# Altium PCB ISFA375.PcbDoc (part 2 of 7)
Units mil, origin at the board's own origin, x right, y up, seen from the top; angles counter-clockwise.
Board outline 5615 x 5520 mil, 6 copper layers (Top_SL, GND, POWER, Signal_Layer, GND2, Bottom_SL), stack 60.472 mil thick; 494 components, 307 nets, 1648 pads, 755 vias.
Unrouted connection lines stored in the file: 315.
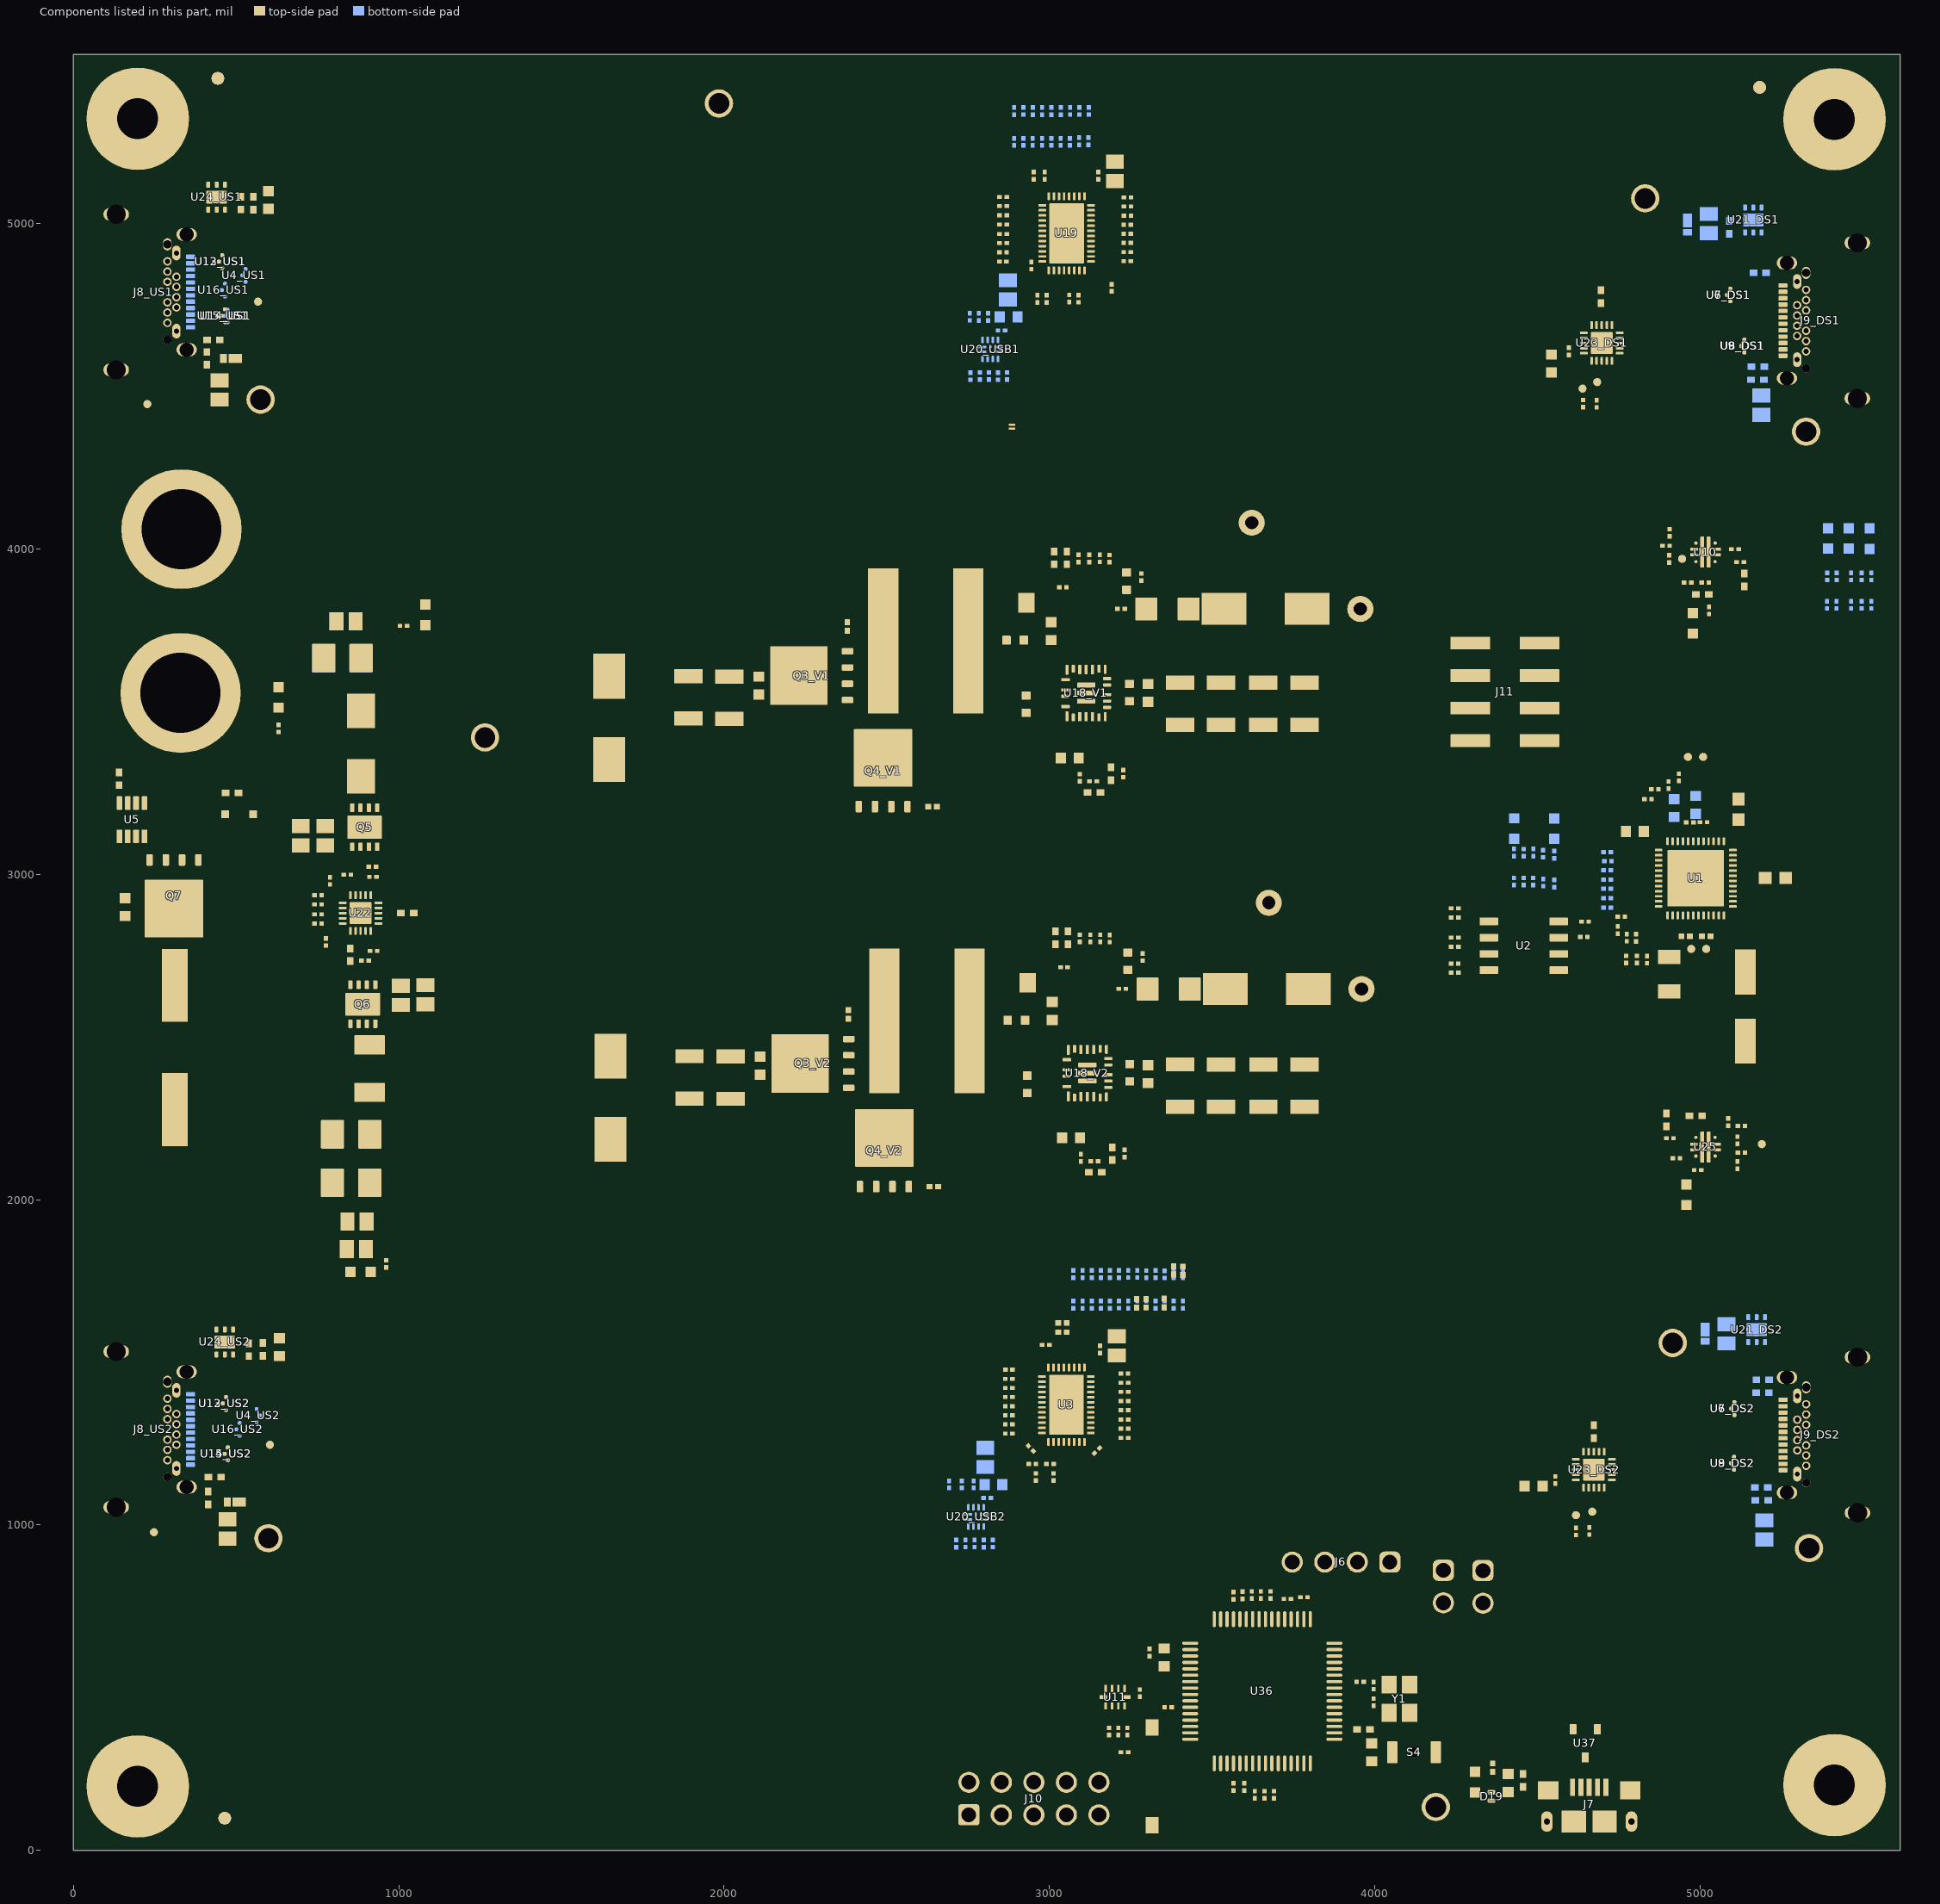
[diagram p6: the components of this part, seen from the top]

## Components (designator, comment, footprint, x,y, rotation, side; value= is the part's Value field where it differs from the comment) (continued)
R173 "RC0201FR-07470RL" 0201L 5464.61,3916.09 r270 bottom value=470
S1 "CHS-01TB" SW_CHS-01TB 3316.08,227.38 r180 top
S4 "B3U-1000P-B" FP-B3U-1000P-B_SMT_SW_3MM_2MM5-MFG 4121.01,301.56 r180 top
TP1 "TESTPOINT" TP_25MIL-SMT 4963,3361.17 r180 top
TP2 "TESTPOINT" TP_25MIL-SMT 5009.5,3361.17 r180 top
TP4 "TESTPOINT" TP_25MIL-SMT 4973,2771 r180 top
TP5 "TESTPOINT" TP_25MIL-SMT 5019,2771 r180 top
TP6 "5005" Keystone5005 1984,5369.96 r90 top
TP7_V1 "5003" Keystone5003 3622,4080.88 r90 top (schematic designator TP7)
TP7_V2 "5003" Keystone5003 3674.46,2912.88 r90 top (schematic designator TP7)
TP8_V1 "5003" Keystone5003 3955.74,3815.9 r90 top (schematic designator TP8)
TP8_V2 "5003" Keystone5003 3959.53,2647.9 r90 top (schematic designator TP8)
TP9_US1 "5005" Keystone5005 575.03,4459.47 r90 top (schematic designator TP9)
TP9_US2 "5005" Keystone5005 599.03,959.47 r90 top (schematic designator TP9)
TP10_DS1 "5005" Keystone5005 4831.4,5078 r90 top (schematic designator TP10)
TP10_DS2 "5005" Keystone5005 4916.03,1559.79 r90 top (schematic designator TP10)
TP11_DS1 "5006" Keystone5006 5326.17,4360.98 r90 top (schematic designator TP11)
TP11_DS2 "5006" Keystone5006 5335.13,928.9 r90 top (schematic designator TP11)
TP12 "5005" Keystone5005 4187.94,133.36 r0 top
TP13_DS1 "TESTPOINT" TP_25MIL-SMT 4683.89,4513.37 r180 top (schematic designator TP13)
TP13_DS2 "TESTPOINT" TP_25MIL-SMT 4668.76,1041.1 r180 top (schematic designator TP13)
TP14_DS1 "TESTPOINT" TP_25MIL-SMT 4638.83,4493.27 r180 top (schematic designator TP14)
TP14_DS2 "TESTPOINT" TP_25MIL-SMT 4618.56,1030.36 r180 top (schematic designator TP14)
TP15 "TESTPOINT" TP_25MIL-SMT 4945,3970 r90 top
TP16 "TESTPOINT" TP_25MIL-SMT 5190.08,2170.94 r90 top
TP17_US1 "TESTPOINT" TP_25MIL-SMT 227,4445.69 r90 top (schematic designator TP17)
TP17_US2 "TESTPOINT" TP_25MIL-SMT 247.32,978 r90 top (schematic designator TP17)
TP18_US1 "TESTPOINT" TP_25MIL-SMT 567.15,4760.47 r90 top (schematic designator TP18)
TP18_US2 "TESTPOINT" TP_25MIL-SMT 603.71,1246.76 r90 top (schematic designator TP18)
TP19 "5005" Keystone5005 1265,3420.76 r0 top
U1 "TPS65994BFRSLR" RSL0048B-MFG 4987,2988 r90 top
U2 "CAT24C256WI-GT3" SOIC-8 4458.22,2780.52 r0 top
U3 "TUSB1044IRNQT" RNQ0040A 3052.24,1369.74 r270 top
U4_US1 "ESD122DMYR" DMY0003A#1 524,4841 r0 bottom (schematic designator U4)
U4_US2 "ESD122DMYR" DMY0003A#1 567.8,1336.58 r180 bottom (schematic designator U4)
U5 "LM74500-Q1DDF" DDF0008A-MFG 179.59,3168.24 r270 top
U6_DS1 "ESD122DMYR" DMY0003A#2 5088.25,4781.01 r0 top (schematic designator U6)
U6_DS2 "ESD122DMYR" DMY0003A#2 5100.46,1357.5 r0 top (schematic designator U6)
U7_DS1 "ESD122DMYR" DMY0003A#1 5088.34,4780.98 r0 bottom (schematic designator U7)
U7_DS2 "ESD122DMYR" DMY0003A#1 5101,1358 r0 bottom (schematic designator U7)
U8_DS1 "ESD122DMYR" DMY0003A#2 5131.83,4624.27 r0 top (schematic designator U8)
U8_DS2 "ESD122DMYR" DMY0003A#2 5100,1190 r0 top (schematic designator U8)
U9_DS1 "ESD122DMYR" DMY0003A#1 5131.54,4623.98 r0 bottom (schematic designator U9)
U9_DS2 "ESD122DMYR" DMY0003A#1 5100,1190 r0 bottom (schematic designator U9)
U10 "LM73100RPWT" -MFG 5016.93,3990.91 r0 top
U11 "TS3USB221RSER" RSE0010A 3202.01,470.96 r270 top
U12_US1 "ESD122DMYR" DMY0003A#1 452.08,4883.32 r0 bottom (schematic designator U12)
U12_US2 "ESD122DMYR" DMY0003A#1 464,1374 r0 bottom (schematic designator U12)
U13_US1 "ESD122DMYR" DMY0003A#2 452.08,4883.32 r0 top (schematic designator U13)
U13_US2 "ESD122DMYR" DMY0003A#2 463.98,1373.75 r0 top (schematic designator U13)
U14_US1 "ESD122DMYR" DMY0003A#1 468.54,4716.48 r0 bottom (schematic designator U14)
U14_US2 "ESD122DMYR" DMY0003A#1 468.9,1218.66 r0 bottom (schematic designator U14)
U15_US1 "ESD122DMYR" DMY0003A#2 460.51,4717.18 r0 top (schematic designator U15)
U15_US2 "ESD122DMYR" DMY0003A#2 470,1219 r0 top (schematic designator U15)
U16_US1 "ESD122DMYR" DMY0003A#1 460.92,4796 r0 bottom (schematic designator U16)
U16_US2 "ESD122DMYR" DMY0003A#1 505.55,1294 r0 bottom (schematic designator U16)
U18_V1 "TPS55288RPMR" RPM0026A 3112.86,3557.36 r90 top (schematic designator U18)
U18_V2 "TPS55288RPMR" RPM0026A 3116.65,2389.36 r90 top (schematic designator U18)
U19 "TUSB1104RNQT" RNQ0040A-MFG 3052.97,4970.45 r270 top
U20_USB1 "TUSB216IRWBT" RWB0012A-MFG 2818.42,4613.74 r180 bottom (schematic designator U20)
U20_USB2 "TUSB216IRWBT" RWB0012A-MFG 2774.43,1025.04 r180 bottom (schematic designator U20)
U21_DS1 "TVS2200DRVR" DRV0006A#1 5164,5011.61 r270 bottom (schematic designator U21)
U21_DS2 "TVS2200DRVR" DRV0006A#1 5174,1600.61 r270 bottom (schematic designator U21)
U22 "TPS51225RUKT" RUK0020B 882.47,2880.95 r0 top
U23_DS1 "TPD6S300ARUKR" RUK0020B 4697.97,4633.37 r270 top (schematic designator U23)
U23_DS2 "TPD6S300ARUKR" RUK0020B 4673.68,1170.32 r270 top (schematic designator U23)
U24_US1 "TVS2200DRVR" DRV0006A#2 440,5081.61 r270 top (schematic designator U24)
U24_US2 "TVS2200DRVR" DRV0006A#2 465,1562.61 r270 top (schematic designator U24)
U25 "LM73100RPWT" -MFG 5016.84,2162 r180 top
U36 "TM4C123GH6PMTR" PM0064A_L 3654.36,489.19 r0 top
U37 "TPD2E009DBZR" DBZ0003A_L 4647.1,329.12 r270 top
Y1 "NX3225GA-16.000M-STD-CRG-1" NDK_NX3225GA 4076,466.36 r180 top

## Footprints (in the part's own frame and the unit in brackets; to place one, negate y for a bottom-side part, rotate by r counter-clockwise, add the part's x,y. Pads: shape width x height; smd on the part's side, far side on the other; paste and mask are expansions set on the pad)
0201 [mm] "Data from Kemet datasheet CC101_COM dated 7/28/11"
  rect 0.46x0.42 smd mask+0.048: 1(-0.33,0) 2(0.33,0)
  body extent -0.31,-0.16 0.31,0.16, height 0.26
0201_033 [mm] "SMD, 2-Leads, Height 0.33mm"
  rect 0.46x0.42 smd mask+0.048: 1(-0.33,0) 2(0.33,0)
  body extent -0.31,-0.16 0.31,0.16, height 0.33
0201_033L [mm] "0201"
  rect 0.36x0.32 smd mask+0.048: 1(-0.28,0) 2(0.28,0)
  body extent -0.31,-0.16 0.31,0.16, height 0.33
0201L [mm] "Data from Kemet datasheet CC101_COM dated 7/28/11"
  rect 0.36x0.32 smd mask+0.048: 1(-0.28,0) 2(0.28,0)
  body extent -0.31,-0.16 0.31,0.16, height 0.26
0402L [mm] "0402 from SM-752 data"
  rect 0.6x0.5 smd: 1(-0.5,0) 2(0.5,0)
  body extent -0.55,-0.3 0.55,0.3, height 0.6
0603 [mm] "0603 from SM-752 data"
  rect 1x0.95 smd: 1(-0.8,0) 2(0.8,0)
  silkscreen extent -1.52,-0.69 1.52,0.69, body extent -0.87,-0.47 0.87,0.47, height 1
0603L [mm] "0603 from SM-752 data"
  rect 0.8x0.85 smd: 1(-0.7,0) 2(0.7,0)
  silkscreen extent -0.07,-0.33 0.07,0.33, body extent -0.87,-0.47 0.87,0.47, height 1
0805L [mm] "0805 from SM-752 data"
  rect 1.1x1.4 smd: 1(-0.75,0) 2(0.75,0)
  body extent -1.1,-0.72 1.1,0.72, height 1.45
1206L [mm] "1206 from SM-752 data"
  rect 1.1x1.75 smd: 1(-1.35,0) 2(1.35,0)
  silkscreen extent -0.4,-0.77 0.4,0.77, body extent -1.7,-0.9 1.7,0.9, height 1.35
1210_280 [mm] "SMD, 2-Leads, Body 3.6x2.8mm, Height 2.8mm"
  rect 1.1x2.2 smd: 1(-1.65,0) 2(1.65,0)
  silkscreen extent -0.84,-1.4 0.84,1.4, body extent -1.8,-1.4 1.8,1.4, height 2.8
3528-21 [mm] "Medium Density IPC, based on Kemet datasheet 2016-10-20"
  rrect6% 1.8x2.23 smd: 1(-1.46,0) 2(1.46,0)
  silkscreen extent -2.29,-1.5 0.76,1.5, body extent -1.85,-1.5 1.85,1.5, height 2.12
-MFG [mm]
  round 0.27 smd paste-1000 mask+0: 1(-0.75,0.7) 10(0.75,0.7)
  rrect40% 0.6x0.25 smd paste+0 mask+0: 2(-0.9,0.225) 3(-0.9,-0.225) 8(0.9,-0.225) 9(0.9,0.225)
  round 0.255 smd paste-1000 mask+0: 4(-0.75,-0.75) 7(0.75,-0.75)
  rrect33% 0.3x2.4 smd paste-1000 mask+0: 5(-0.25,0) 6(0.25,0)
  Top_SL region: 0.85,-0.85 0.85,-1.15 0.846,-1.169 0.835,-1.185 0.819,-1.196 0.8,-1.2 0.8,-1.2 0.65,-1.2 0.631,-1.196 0.615,-1.185 0.604,-1.169 0.6,-1.15 0.6,-1.15 0.6,-0.6 0.604,-0.581 0.615,-0.565 0.631,-0.554 0.65,-0.55 0.65,-0.55 1.15,-0.55 1.169,-0.554 1.185,-0.565 1.196,-0.581 1.2,-0.6 1.2,-0.6 1.2,-0.8 1.196,-0.819 1.185,-0.835 1.169,-0.846 1.15,-0.85 1.15,-0.85
  Top_SL region: -0.85,0.85 -0.85,1.15 -0.843,1.175 -0.825,1.193 -0.8,1.2 -0.8,1.2 -0.65,1.2 -0.631,1.196 -0.615,1.185 -0.604,1.169 -0.6,1.15 -0.6,1.15 -0.6,0.6 -0.604,0.581 -0.615,0.565 -0.631,0.554 -0.65,0.55 -0.65,0.55 -1.15,0.55 -1.169,0.554 -1.185,0.565 -1.196,0.581 -1.2,0.6 -1.2,0.6 -1.2,0.8 -1.193,0.825 -1.175,0.843 -1.15,0.85 -1.15,0.85
  Top_SL region: -0.85,-0.85 -0.85,-1.15 -0.846,-1.169 -0.835,-1.185 -0.819,-1.196 -0.8,-1.2 -0.8,-1.2 -0.65,-1.2 -0.631,-1.196 -0.615,-1.185 -0.604,-1.169 -0.6,-1.15 -0.6,-1.15 -0.6,-0.6 -0.604,-0.581 -0.615,-0.565 -0.631,-0.554 -0.65,-0.55 -0.65,-0.55 -1.15,-0.55 -1.169,-0.554 -1.185,-0.565 -1.196,-0.581 -1.2,-0.6 -1.2,-0.6 -1.2,-0.8 -1.196,-0.819 -1.185,-0.835 -1.169,-0.846 -1.15,-0.85 -1.15,-0.85
  Top_SL region: 0.85,0.85 0.85,1.15 0.846,1.169 0.835,1.185 0.819,1.196 0.8,1.2 0.8,1.2 0.65,1.2 0.631,1.196 0.615,1.185 0.604,1.169 0.6,1.15 0.6,1.15 0.6,0.6 0.604,0.581 0.615,0.565 0.631,0.554 0.65,0.55 0.65,0.55 1.15,0.55 1.169,0.554 1.185,0.565 1.196,0.581 1.2,0.6 1.2,0.6 1.2,0.8 1.196,0.819 1.185,0.835 1.169,0.846 1.15,0.85 1.15,0.85
  silkscreen extent -1.87,-1.58 1.05,1.58, body extent -1.3,-1.3 1.3,1.3, height 0.25
CAPSMT_62_F61 [mm] "6.3 x 5.8mm:  Chemi-Con F61"
  rect 3.5x1.6 smd: 1(-2.675,0.025) 2(2.725,0.025)
  silkscreen extent -3.34,-3.38 3.46,3.42, body extent -3.37,-3.38 3.46,3.43, height 6.1
CE_Mark_5mm [mil] "Minimum text height for CE Mark"
  silkscreen extent -138,-98 138,98
DBZ0003A_L [mm] "SOT23, 3-Leads, Body 2.9x1.3mm, Pitch 0.95mm, Lead Span 2.4mm, IPC High Density"
  rrect18% 0.8x0.55 smd: 1(-1.1,0.95) 2(-1.1,-0.95) 3(1.1,0)
  silkscreen extent 0.2,-1.5 0.7,1.5, body extent -1.26,-1.46 1.26,1.46, height 0.98
DDF0008A-MFG [mm]
  rrect22% 1.05x0.45 smd paste+0 mask+0: 1(-1.3,0.975) 2(-1.3,0.325) 3(-1.3,-0.325) 4(-1.3,-0.975) 5(1.3,-0.975) 6(1.3,-0.325) 7(1.3,0.325) 8(1.3,0.975)
  silkscreen extent -2.5,-1.48 0.4,1.48, body extent -1.41,-1.45 1.41,1.45, height 1.1
DMY0003A#1 [mm]
  rrect67% 0.3x0.3 smd paste-0.3 mask-0.05: 1(-0.125,0) 2(0.125,-0.5) 3(0.125,0.5)
  rrect48% 0.21x0.21 on Bottom Paste: 1(-0.125,0) 2(0.125,-0.5) 3(0.125,0.5)
  body extent -0.35,-0.7 0.35,0.7, height 0.4
DMY0003A#2 [mm]
  rrect67% 0.3x0.3 smd paste-0.3 mask-0.05: 1(-0.125,0) 2(0.125,-0.5) 3(0.125,0.5)
  rrect48% 0.21x0.21 on Top Paste: 1(-0.125,0) 2(0.125,-0.5) 3(0.125,0.5)
  body extent -0.35,-0.7 0.35,0.7, height 0.4
DPY0002A [mm] "X1SON-2"
  rrect57% 0.35x0.6 smd paste-0.5 mask-0.05: 1(-0.325,0) 2(0.325,0)
  rrect33% 0.3x0.5 on Top Paste: 1S(-0.35,0) 2S(0.35,0)
  silkscreen extent -0.85,-0.03 -0.8,0.02, body extent -0.5,-0.3 0.5,0.3, height 0.45
DQJ0008A [mm] "SMD, 8-Leads, Body 5.75x4.9mm"
  rrect39% 0.91x0.51 smd paste-0.05 mask-0.05: 1(-2.795,1.905) 2(-2.795,0.635) 3(-2.795,-0.635) 4(-2.795,-1.905) 5(2.795,-1.905) 6(2.795,-0.635) 7(2.795,0.635) 8(2.795,1.905)
  rrect8% 1.58x1.25 on Top Paste: 9(-0.38,1.45) 9(-0.38,0) 9(-0.38,-1.45) 9(1.4,1.45) 9(1.4,0) 9(1.4,-1.45)
  rrect3% 3.48x4.47 on Top Solder: 9(0.55,0)
  rrect2% 4.49x4.57 smd paste-2.5 mask-2.5: 9(1.005,0)
  silkscreen extent -3,-2.6 3,2.6, body extent -3.13,-2.45 3.13,2.45, height 1.15
DQZ0008A [mm] "SON, 8-Leads, Body 3.3x3.3mm, Pitch 0.65mm"
  rrect29% 0.65x0.34 smd mask+0: 1(-1.525,0.975) 2(-1.525,0.325)
  rrect29% 0.65x0.34 smd: 3(-1.525,-0.325) 4(-1.525,-0.975) 5(1.525,-0.975) 6(1.525,-0.325) 7(1.525,0.325) 8(1.525,0.975)
  rrect50% 0.2x0.3 on Top Paste: 9(-0.59,1.7) 9(-0.59,-1.7) 9(0.59,1.7) 9(0.59,-1.7)
  rrect8% 1.63x1.19 on Top Paste: 9(0,0.695) 9(0,-0.695)
  rrect6% 1.8x2.7 smd paste-1: 9(0,0)
  Top_SL region: -0.49,1.85 -0.69,1.85 -0.69,-1.85 -0.49,-1.85
  Top_SL region: 0.49,-1.85 0.69,-1.85 0.69,1.85 0.49,1.85
  Top_SL region: -1.9,0.205 -1.9,1.095 -1.892,1.133 -1.871,1.166 -1.838,1.187 -1.8,1.195 -1.8,1.195 -1.25,1.195 -1.212,1.187 -1.179,1.166 -1.158,1.133 -1.15,1.095 -1.15,1.095 -1.15,0.205 -1.158,0.167 -1.179,0.134 -1.212,0.113 -1.25,0.105 -1.25,0.105 -1.8,0.105 -1.838,0.113 -1.871,0.134 -1.892,0.167 -1.9,0.205
  silkscreen extent -1.8,-1.8 1.8,1.8, body extent -1.7,-1.7 1.7,1.7, height 1.56
DRV0006A#1 [mm] "SON, 6-Leads, Body 2x2mm, Pitch 0.65mm, Thermal Pad 1.6x1mm, TI Recommended"
  rrect33% 0.45x0.3 smd: 1(-0.975,0.65) 2(-0.975,0) 3(-0.975,-0.65) 4(0.975,-0.65) 5(0.975,0) 6(0.975,0.65)
  rrect14% 1x0.7 on Bottom Paste: 7(0,-0.45) 7(0,0.45)
  rrect10% 1x1.6 smd paste-0.5: 7(0,0)
  silkscreen extent -1.05,-1.2 1.05,1.2, body extent -1.05,-1.05 1.05,1.05, height 0.81
DRV0006A#2 [mm] "SON, 6-Leads, Body 2x2mm, Pitch 0.65mm, Thermal Pad 1.6x1mm, TI Recommended"
  rrect33% 0.45x0.3 smd: 1(-0.975,0.65) 2(-0.975,0) 3(-0.975,-0.65) 4(0.975,-0.65) 5(0.975,0) 6(0.975,0.65)
  rrect14% 1x0.7 on Top Paste: 7(0,0.45) 7(0,-0.45)
  rrect10% 1x1.6 smd paste-0.5: 7(0,0)
  silkscreen extent -1.05,-1.2 1.05,1.2, body extent -1.05,-1.05 1.05,1.05, height 0.81
DSN2_0603 [mm] "SMD, 2-Leads, Body 1.6x0.8mm"
  rect 0.52x0.7 smd: 1(-0.64,0)
  rect 1.05x0.7 smd: 2(0.275,0)
  silkscreen extent -1.4,-0.75 0.8,0.75, body extent -0.8,-0.4 0.8,0.4, height 0.31
FCC_disclaimer [mil]
FCI_10118193-0001LF [mm] "Connector, Receptacle, USB Micro B, R/A, SMT"
  rect 0.4x1.35 smd: 1(-1.3,4.125) 2(-0.65,4.125) 3(0,4.125) 4(0.65,4.125) 5(1.3,4.125)
  oval 0.9x1.6 hole 0.5 slot 1.2 at 90 deg: 6(-3.3,1.45) 7(3.3,1.45)
  rect 1.6x1.4 smd: 8(-3.2,3.9) 9(3.2,3.9)
  rect 1.9x1.7 smd: 10(-1.2,1.45) 11(1.2,1.45)
  silkscreen extent -4.3,0.2 4.3,5.4, body extent -3.93,-1.45 3.93,4.5, height 3.51
Fiducial10-20 [mm]
  round 1 smd mask+0.5: 1(0,0)
  Top_SL keep-out circle w1.178: c0,0 r0.5
FP-632723130112_CONN_USB_9MM65_10MM0-MFG#1 [mm]
  rrect100% 1x1.6 hole 1.1 slot 0.5 at 0 deg paste-1000 mask+0: 1(-4.5,4.26) 2(4.5,4.26)
  rrect100% 1x2 hole 1.5 slot 0.5 at 0 deg paste-1000 mask+0: 3(-6.075,-1.24) 4(6.075,-1.24)
  rrect29% 0.347x0.7 smd paste+0 mask+0: A1(-2.75,4.57) A2(-2.25,4.57) A3(-1.75,4.57) A4(-1.25,4.57) A5(-0.75,4.57) A6(-0.25,4.57) A7(0.25,4.57) A8(0.75,4.57) A9(1.25,4.57) A10(1.75,4.57) A11(2.25,4.57) A12(2.75,4.57)
  rrect100% 1.15x0.65 hole 0.4 slot 0.9 at 0 deg paste-1000 mask+0: B1(3.05,3.46) B12(-3.05,3.46)
  round 0.65 hole 0.4 paste-1000 mask+0: B2(2.4,2.76) B3(1.6,2.76) B4(1.2,3.46) B5(0.8,2.76) B6(0.4,3.46) B7(-0.4,3.46) B8(-0.8,2.76) B9(-1.2,3.46) B10(-1.6,2.76) B11(-2.4,2.76)
  round 0.65 hole 0.65 unplated paste-1000 mask+0: ""(-3.725,2.76)
  rrect100% 0.95x0.65 hole 0.65 slot 0.95 at 0 deg unplated paste-1000 mask+0: ""(3.725,2.76)
  silkscreen extent -5.63,0.14 5.63,5.99, body extent -6.17,-4.99 6.17,5, height 2.05
FP-632723130112_CONN_USB_9MM65_10MM0-MFG#2 [mm]
  rrect100% 1x1.6 hole 1.1 slot 0.5 at 0 deg paste-1000 mask+0: 1(-4.5,4.26) 2(4.5,4.26)
  rrect100% 1x2 hole 1.5 slot 0.5 at 0 deg paste-1000 mask+0: 3(-6.075,-1.24) 4(6.075,-1.24)
  rrect29% 0.35x0.7 smd paste+0 mask+0: A1(-2.75,4.57) A2(-2.25,4.57) A3(-1.75,4.57) A4(-1.25,4.57) A5(-0.75,4.57) A6(-0.25,4.57) A7(0.25,4.57) A8(0.75,4.57) A9(1.25,4.57) A10(1.75,4.57) A11(2.25,4.57) A12(2.75,4.57)
  rrect100% 1.15x0.65 hole 0.4 slot 0.9 at 0 deg paste-1000 mask+0: B1(3.05,3.46) B12(-3.05,3.46)
  round 0.65 hole 0.4 paste-1000 mask+0: B2(2.4,2.76) B3(1.6,2.76) B4(1.2,3.46) B5(0.8,2.76) B6(0.4,3.46) B7(-0.4,3.46) B8(-0.8,2.76) B9(-1.2,3.46) B10(-1.6,2.76) B11(-2.4,2.76)
  round 0.65 hole 0.65 unplated paste-1000 mask+0: ""(-3.725,2.76)
  rrect100% 0.95x0.65 hole 0.65 slot 0.95 at 0 deg unplated paste-1000 mask+0: ""(3.725,2.76)
  silkscreen extent -5.63,0.14 5.63,5.99, body extent -6.17,-4.99 6.17,5, height 2.05
FP-B3U-1000P-B_SMT_SW_3MM_2MM5-MFG [mm]
  rrect13% 0.8x1.7 smd paste+0 mask+0: 1(-1.7,0) 2(1.7,0)
  round 0.75 hole 0.75 unplated paste-1000 mask+0: ""(0,0)
  silkscreen extent -1.6,-1.35 1.6,1.35, body extent -2,-1.25 2,1.25, height 1.75
FP-CRF1206-FZ-R010ELF_1206-MFG [mm]
  rrect6% 1.7x1.8 smd paste+0 mask+0: 1(-1.65,0) 2(1.65,0)
  silkscreen extent -0.43,-0.92 0.43,0.92, body extent -2.6,-1.02 2.6,1.02, height 0.25
FP-GCM188L81H104KA57D_0603-MFG [mm]
  rrect15% 0.65x0.7 smd paste+0 mask+0: 1(-0.675,0) 2(0.675,0)
  body extent -1.1,-0.55 1.1,0.55, height 0.25
Hirschmann_930_176-100 [mm] "Banana Jack BIL 20 Black, TH"
  round 9.375 hole 6.25: 1(0,0)
  body extent -5,-5 5,5, height 12
Hirschmann_930_176-101 [mm] "Banana Jack BIL 20 Red, TH"
  round 9.375 hole 6.25: 1(0,0)
  body extent -5,-5 5,5, height 12
Keystone5003 [mil] "For Keystone 500x miniature loop terminals"
  round 80 hole 40: 1(0,0)
  silkscreen extent -52,-52 52,52, body extent -49,-49 49,49, height 182
Keystone5005 [mil] "Keystone Compact loops"
  round 87 hole 63: 1(0,0)
  silkscreen extent -70,-70 70,70, body extent -63,-63 62,63, height 225
Keystone5006 [mil] "Keystone Compact loops"
  round 87 hole 63: 1(0,0)
  silkscreen extent -70,-70 70,70, body extent -63,-63 62,63, height 225
NDK_NX3225GA [mm] "NDK"
  rect 1.2x1.4 smd: 1(-0.8,1.1) 2(-0.8,-1.1) 3(0.8,-1.1) 4(0.8,1.1)
  silkscreen extent -1.9,-0.1 1.4,2, body extent -1.3,-1.65 1.3,1.65, height 0.9
Net-Tie6milsWide_20milsLong [mil] "6 mils wide by 20 mils long"
  rect 10x6 smd paste-5 mask-5: 1(-5,0) 2(5,0)
Net-Tie_6x8mil [mil] "Net Tie 0402 size"
  rect 4x6 smd paste-5 mask-5: 1(-2,0) 2(2,0)
Net-Tie_50milWide_30milLong [mil] "50mil net tie, no solder mask opening, no solder paste"
  rect 30x50 smd paste-20 mask-20: 1(-15,0) 2(15,0)
"NY PMS 440 0025 PH" [mm] "4-40 nylon screw and mounting hole"
  round 8 hole 3.2: 1(0,0)
  body extent -3.3,-3.3 3.3,3.3, height 2.69
PM0064A_L [mm] "Thin QFP, 64-Leads, Body 10x10mm, Pitch 0.5mm, IPC High Density"
  oval 1.25x0.25 smd: 1(-5.625,3.75) 2(-5.625,3.25) 3(-5.625,2.75) 4(-5.625,2.25) 5(-5.625,1.75) 6(-5.625,1.25) 7(-5.625,0.75) 8(-5.625,0.25) 9(-5.625,-0.25) 10(-5.625,-0.75) 11(-5.625,-1.25) 12(-5.625,-1.75) 13(-5.625,-2.25) 14(-5.625,-2.75) 15(-5.625,-3.25) 16(-5.625,-3.75) 33(5.625,-3.75) 34(5.625,-3.25) 35(5.625,-2.75) 36(5.625,-2.25) 37(5.625,-1.75) 38(5.625,-1.25) 39(5.625,-0.75) 40(5.625,-0.25) 41(5.625,0.25) 42(5.625,0.75) 43(5.625,1.25) 44(5.625,1.75) 45(5.625,2.25) 46(5.625,2.75) 47(5.625,3.25) 48(5.625,3.75)
  oval 0.25x1.25 smd: 17(-3.75,-5.625) 18(-3.25,-5.625) 19(-2.75,-5.625) 20(-2.25,-5.625) 21(-1.75,-5.625) 22(-1.25,-5.625) 23(-0.75,-5.625) 24(-0.25,-5.625) 25(0.25,-5.625) 26(0.75,-5.625) 27(1.25,-5.625) 28(1.75,-5.625) 29(2.25,-5.625) 30(2.75,-5.625) 31(3.25,-5.625) 32(3.75,-5.625) 49(3.75,5.625) 50(3.25,5.625) 51(2.75,5.625) 52(2.25,5.625) 53(1.75,5.625) 54(1.25,5.625) 55(0.75,5.625) 56(0.25,5.625) 57(-0.25,5.625) 58(-0.75,5.625) 59(-1.25,5.625) 60(-1.75,5.625) 61(-2.25,5.625) 62(-2.75,5.625) 63(-3.25,5.625) 64(-3.75,5.625)
  silkscreen extent -5.65,-4.35 4.35,4.55, body extent -6.01,-6.01 6.01,6.01, height 1.5
RNQ0040A [mm] "SMD, 40-Leads, Body 6x4mm, Pitch 0.4mm"
  rrect50% 0.6x0.2 smd: 1(-2.9,1.4) 2(-2.9,1) 3(-2.9,0.6) 4(-2.9,0.2) 5(-2.9,-0.2) 6(-2.9,-0.6) 7(-2.9,-1) 8(-2.9,-1.4) 21(2.9,-1.4) 22(2.9,-1) 23(2.9,-0.6) 24(2.9,-0.2) 25(2.9,0.2) 26(2.9,0.6) 27(2.9,1) 28(2.9,1.4)
  rrect50% 0.2x0.6 smd: 9(-2.2,-1.9) 10(-1.8,-1.9) 11(-1.4,-1.9) 12(-1,-1.9) 13(-0.6,-1.9) 14(-0.2,-1.9) 15(0.2,-1.9) 16(0.6,-1.9) 17(1,-1.9) 18(1.4,-1.9) 19(1.8,-1.9) 20(2.2,-1.9) 29(2.2,1.9) 30(1.8,1.9) 31(1.4,1.9) 32(1,1.9) 33(0.6,1.9) 34(0.2,1.9) 35(-0.2,1.9) 36(-0.6,1.9) 37(-1,1.9) 38(-1.4,1.9) 39(-1.8,1.9) 40(-2.2,1.9)
  rrect4% 4.7x2.7 smd paste-5: 41(0,0)
  body extent -3,-2 3,2, height 0.8
RNQ0040A-MFG [mm]
  rrect50% 0.6x0.2 smd paste+0 mask+0: 1(-2.9,1.4) 2(-2.9,1) 3(-2.9,0.6) 4(-2.9,0.2) 5(-2.9,-0.2) 6(-2.9,-0.6) 7(-2.9,-1) 8(-2.9,-1.4) 21(2.9,-1.4) 22(2.9,-1) 23(2.9,-0.6) 24(2.9,-0.2) 25(2.9,0.2) 26(2.9,0.6) 27(2.9,1) 28(2.9,1.4)
  rrect50% 0.2x0.6 smd paste+0 mask+0: 9(-2.2,-1.9) 10(-1.8,-1.9) 11(-1.4,-1.9) 12(-1,-1.9) 13(-0.6,-1.9) 14(-0.2,-1.9) 15(0.2,-1.9) 16(0.6,-1.9) 17(1,-1.9) 18(1.4,-1.9) 19(1.8,-1.9) 20(2.2,-1.9) 29(2.2,1.9) 30(1.8,1.9) 31(1.4,1.9) 32(1,1.9) 33(0.6,1.9) 34(0.2,1.9) 35(-0.2,1.9) 36(-0.6,1.9) 37(-1,1.9) 38(-1.4,1.9) 39(-1.8,1.9) 40(-2.2,1.9)
  rrect4% 4.7x2.7 smd paste-1000 mask+0: 41(0,0)
  silkscreen extent -3.9,-2.05 3.05,2.05, body extent -3.3,-2.3 3.3,2.3, height 0.25
RPM0026A [mm] "VQFN-HR-26"
  rrect44% 0.775x0.225 smd: 1(-1.813,1.487) 19(1.813,1.487)
  rrect40% 0.6x0.25 smd: 2(-1.9,1) 6(-1.9,-1) 14(1.9,-1) 18(1.9,1)
  rrect40% 0.725x0.25 smd: 3(-1.838,0.5) 4(-1.838,0) 5(-1.838,-0.5) 15(1.837,-0.5) 16(1.837,0) 17(1.837,0.5)
  rrect44% 0.7x0.225 smd: 7(-1.85,-1.488) 13(1.85,-1.488)
  rrect40% 0.25x0.625 smd: 8(-1.125,-1.638) 9(-0.625,-1.638) 10(-0.125,-1.638) 11(0.625,-1.638) 12(1.125,-1.638)
  rrect40% 0.25x0.675 smd: 20(1.05,1.612) 23(-1.05,1.612)
  rrect40% 0.25x0.6 smd: 21(0.25,1.65) 22(-0.25,1.65)
  rrect27% 0.375x1.425 smd: 24(-0.625,0) 25(0,0) 26(0.625,0)
  Top_SL region: -2.15,-1.6 -2.169,-1.596 -2.185,-1.585 -2.196,-1.569 -2.2,-1.55 -2.2,-1.55 -2.2,-1.425 -2.196,-1.406 -2.185,-1.39 -2.169,-1.379 -2.15,-1.375 -2.15,-1.375 -1.55,-1.375 -1.531,-1.379 -1.515,-1.39 -1.504,-1.406 -1.5,-1.425 -1.5,-1.425 -1.5,-1.9 -1.504,-1.919 -1.515,-1.935 -1.531,-1.946 -1.55,-1.95 -1.55,-1.95 -1.8,-1.95 -1.819,-1.946 -1.835,-1.935 -1.846,-1.919 -1.85,-1.9 -1.85,-1.9 -1.85,-1.6
  Top_SL region: 1.5,-1.9 1.504,-1.919 1.515,-1.935 1.531,-1.946 1.55,-1.95 1.55,-1.95 1.8,-1.95 1.819,-1.946 1.835,-1.935 1.846,-1.919 1.85,-1.9 1.85,-1.9 1.85,-1.6 2.15,-1.6 2.169,-1.596 2.185,-1.585 2.196,-1.569 2.2,-1.55 2.2,-1.55 2.2,-1.425 2.196,-1.406 2.185,-1.39 2.169,-1.379 2.15,-1.375 2.15,-1.375 1.55,-1.375 1.531,-1.379 1.515,-1.39 1.504,-1.406 1.5,-1.425 1.5,-1.425
  Top_SL region: 1.425,1.425 1.429,1.406 1.44,1.39 1.456,1.379 1.475,1.375 1.475,1.375 2.15,1.375 2.169,1.379 2.185,1.39 2.196,1.406 2.2,1.425 2.2,1.425 2.2,1.55 2.196,1.569 2.185,1.585 2.169,1.596 2.15,1.6 2.15,1.6 1.825,1.6 1.825,1.9 1.821,1.919 1.81,1.935 1.794,1.946 1.775,1.95 1.775,1.95 1.475,1.95 1.456,1.946 1.44,1.935 1.429,1.919 1.425,1.9 1.425,1.9
  Top_SL region: -2.15,1.375 -2.169,1.379 -2.185,1.39 -2.196,1.406 -2.2,1.425 -2.2,1.425 -2.2,1.55 -2.193,1.575 -2.175,1.593 -2.15,1.6 -2.15,1.6 -1.825,1.6 -1.825,1.9 -1.821,1.919 -1.81,1.935 -1.794,1.946 -1.775,1.95 -1.775,1.95 -1.475,1.95 -1.456,1.946 -1.44,1.935 -1.429,1.919 -1.425,1.9 -1.425,1.9 -1.425,1.425 -1.429,1.406 -1.44,1.39 -1.456,1.379 -1.475,1.375 -1.475,1.375
  body extent -2,-1.75 2,1.75, height 1
RSE0010A [mm] "QFN, 10-Leads, Body 1.5x2mm, Pitch 0.5mm, TI Recommended"
  rect 0.55x0.2 smd: 1(-0.675,0.75) 2(-0.675,0.25) 3(-0.675,-0.25) 4(-0.675,-0.75) 6(0.675,-0.75) 7(0.675,-0.25) 8(0.675,0.25) 9(0.675,0.75)
  rect 0.3x0.6 smd: 5(0,-0.9) 10(0,0.9)
  silkscreen extent -1.07,-1.17 0.77,1.18, body extent -0.77,-1.02 0.78,1.03, height 0.61
RSL0048B-MFG [mm]
  rrect50% 0.6x0.2 smd paste+0 mask+0: 1(-2.9,2.2) 2(-2.9,1.8) 3(-2.9,1.4) 4(-2.9,1) 5(-2.9,0.6) 6(-2.9,0.2) 7(-2.9,-0.2) 8(-2.9,-0.6) 9(-2.9,-1) 10(-2.9,-1.4) 11(-2.9,-1.8) 12(-2.9,-2.2) 25(2.9,-2.2) 26(2.9,-1.8) 27(2.9,-1.4) 28(2.9,-1) 29(2.9,-0.6) 30(2.9,-0.2) 31(2.9,0.2) 32(2.9,0.6) 33(2.9,1) 34(2.9,1.4) 35(2.9,1.8) 36(2.9,2.2)
  rrect50% 0.2x0.6 smd paste+0 mask+0: 13(-2.2,-2.9) 14(-1.8,-2.9) 15(-1.4,-2.9) 16(-1,-2.9) 17(-0.6,-2.9) 18(-0.2,-2.9) 19(0.2,-2.9) 20(0.6,-2.9) 21(1,-2.9) 22(1.4,-2.9) 23(1.8,-2.9) 24(2.2,-2.9) 37(2.2,2.9) 38(1.8,2.9) 39(1.4,2.9) 40(1,2.9) 41(0.6,2.9) 42(0.2,2.9) 43(-0.2,2.9) 44(-0.6,2.9) 45(-1,2.9) 46(-1.4,2.9) 47(-1.8,2.9) 48(-2.2,2.9)
  rrect2% 4.4x4.4 smd paste-1000 mask+0: 49(0,0)
  silkscreen extent -3.9,-3.05 3.05,3.05, body extent -3.3,-3.3 3.3,3.3, height 0.25
RUK0020B [mm]
  rrect50% 0.6x0.2 smd: 1(-1.4,0.8) 2(-1.4,0.4) 3(-1.4,0) 4(-1.4,-0.4) 5(-1.4,-0.8) 11(1.4,-0.8) 12(1.4,-0.4) 13(1.4,0) 14(1.4,0.4) 15(1.4,0.8)
  rrect50% 0.2x0.6 smd: 6(-0.8,-1.4) 7(-0.4,-1.4) 8(0,-1.4) 9(0.4,-1.4) 10(0.8,-1.4) 16(0.8,1.4) 17(0.4,1.4) 18(0,1.4) 19(-0.4,1.4) 20(-0.8,1.4)
  rrect13% 0.75x0.75 on Top Paste: 21(-0.475,-0.475) 21(-0.475,0.475) 21(0.475,-0.475) 21(0.475,0.475)
  rrect6% 1.7x1.7 smd paste-0.85: 21(0,0)
  silkscreen extent -1.68,-1.68 1.68,1.68, body extent -1.5,-1.5 1.5,1.5, height 0.8
RWB0012A-MFG [mm]
  rrect50% 0.7x0.2 smd paste-1000 mask+0: 1(-0.65,0.2) 2(-0.65,-0.2) 7(0.65,-0.2) 8(0.65,0.2)
  rrect50% 0.2x0.5 smd paste+0 mask+0: 3(-0.6,-0.75) 4(-0.2,-0.75) 5(0.2,-0.75) 6(0.6,-0.75) 9(0.6,0.75) 10(0.2,0.75) 11(-0.2,0.75) 12(-0.6,0.75)
  silkscreen extent -1.68,-1.38 0.8,1.38, body extent -0.8,-0.8 0.8,0.8, height 0.4
SM_RADIAL_8MM [mm] "Nichicon 8x10"
  rect 3.5x2.5 smd: 1(-3.25,0) 2(3.25,0)
  silkscreen extent -4.25,-4.25 4.25,4.25, body extent -4.25,-4.25 4.25,4.25, height 10.5
SM_RADIAL_H13 [mm] "12.5 x 13.5mm:  Panasonic H13"
  rect 5.7x2 smd: 1(-4.85,0) 2(4.85,0)
  silkscreen extent -6.85,-6.85 6.85,6.85, body extent -6.85,-6.85 6.85,6.85, height 14
SOD-323-Bi [mm] "SOD323, 2-Leads, Body 1.9x1.45mm, No Polarity Mark"
  rect 0.6x0.6 smd paste-0.05: 1(-1.1,0) 2(1.1,0)
  silkscreen extent -1.53,-0.77 1.53,0.77, body extent -1.27,-0.65 1.27,0.65, height 1.02
SOIC-8 [mm] "duplicate of SO-8.  SOIC, 8-Leads, Body 5.0x4.0mm (max), Pitch 1.27mm, IPC Medium Density"
  rrect17% 1.45x0.6 smd: 1(-2.725,1.905) 2(-2.725,0.635) 3(-2.725,-0.635) 4(-2.725,-1.905) 5(2.725,-1.905) 6(2.725,-0.635) 7(2.725,0.635) 8(2.725,1.905)
  silkscreen extent -3.5,-2.5 0.9,2.5, body extent -3,-2.45 3,2.45, height 1.63
SW_CHS-01TB [mm] "CHS Recommended footprint"
  rect 1x1.27 smd: 1(0,3.81) 2(0,-3.81)
  silkscreen extent -1.8,-4.05 1.3,4.05, body extent -1.25,-4 1.25,4, height 2.51
TI_Stacked_Overlay_Small [mil]
  silkscreen extent -418,-98 418,98
TP_25MIL-SMT [mil]
  round 25 smd mask-2.5: 1(0,0)
WE-HCI_7050 [mm] "Wurth Electronik recommended land pattern"
  rect 2.7x2.2 smd: 1(-2.55,0) 2(2.55,0)
  silkscreen extent -3.7,-3.7 3.7,3.7, body extent -3.6,-3.6 3.6,3.6, height 5
WE-LHMI_4020 [mm] "WERTH"
  rrect7% 1.5x2.4 smd: 1(-1.85,0) 2(1.85,0)
  silkscreen extent -2.2,-2.2 2.2,2.2, body extent -2.15,-2.15 2.15,2.15, height 2
WEEE_Minimum [mil] "WEEElie bin"
  silkscreen extent -95,-172 99,104
WL-SMCW_GREEN [mm] "WURTH"
  rect 0.8x0.8 smd: 1(-0.8,0) 2(0.8,0)
  silkscreen extent -1.9,-0.8 1.2,0.8, body extent -0.85,-0.45 0.85,0.45, height 0.8
Wurth_61000821121 [mm] "Header, 2.54mm, 4x2, SMT"
  rrect10% 3.1x1 smd: 1(-2.7,3.81) 2(2.7,3.81) 3(-2.7,1.27) 4(2.7,1.27) 5(-2.7,-1.27) 6(2.7,-1.27) 7(-2.7,-3.81) 8(2.7,-3.81)
  body extent -3.75,-5.08 3.75,5.08, height 9.6
WURTH_61300211121 [mm] "Header, 2.54mm, 2x1, TH"
  rrect50% 1.65x1.65 hole 1.15: 1(-1.27,0)
  round 1.65 hole 1.15: 2(1.27,0)
  body extent -2.54,-1.27 2.54,1.27, height 8.54
WURTH_61300411121 [mm] "Header, 2.54mm, 4x1, TH"
  rrect50% 1.65x1.65 hole 1.15: 1(-3.81,0)
  round 1.65 hole 1.15: 2(-1.27,0) 3(1.27,0) 4(3.81,0)
  body extent -5.08,-1.27 5.08,1.27, height 8.54
WURTH_61301021121 [mm] "Header, 2.54mm, 5x2, TH"
  rrect25% 1.65x1.65 hole 1.15: 1(-5.08,-1.27)
  round 1.65 hole 1.15: 2(-5.08,1.27) 3(-2.54,-1.27) 4(-2.54,1.27) 5(0,-1.27) 6(0,1.27) 7(2.54,-1.27) 8(2.54,1.27) 9(5.08,-1.27) 10(5.08,1.27)
  silkscreen extent -6.35,-2.9 6.35,2.54, body extent -6.35,-2.54 6.35,2.54, height 8.54
XAL1010 [mm] "COILCRAFT"
  rect 2.38x11.31 smd: 1(-3.325,0) 2(3.325,0)
  silkscreen extent -5.3,-6 5.3,6, body extent -5.25,-5.9 5.25,5.9, height 10

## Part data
C1 C2 C6 C7: library part CMP-0009652-3, "CAP, CERM, 220 pF, 50 V, +/- 10%, X7R, AEC-Q200 Grade 1, 0201", Cap_Case=0201_033, Manufacturer=TDK, Supplier Part Number 1=445-12109-1-ND, TempCo=X7R, Tolerance_%=10%, Value1="11.6275 ohm", Value2=50V, ValueDisplayed=220pF
C3 C5 C104: library part CMP-0006619-2, "CAP, CERM, 1 uF, 35 V, +/- 10%, X5R, 0402", Cap_Case=0402, Manufacturer=MuRata, Supplier Part Number 1=490-10019-1-ND, TempCo=X5R, Tolerance_%=10%, Value1=Unknown, Value2=35V, ValueDisplayed=1uF
C4 C8 C9 C11 C86: library part CMP-0007344-5, "CAP, CERM, 10 uF, 25 V, +/- 20%, X5R, 0603", Cap_Case=0603, Manufacturer=MuRata, Supplier Part Number 1=490-7202-1-ND, TempCo=X5R, Tolerance_%=20%, Value1=Unknown, Value2=25V, ValueDisplayed=10uF
C10: library part CMP-0010560-1, "CAP, AL, 120 uF, 10 V, +/- 20%, 0.025 ohm, SMD", Cap_Case=F61, Manufacturer=Chemi-Con, Supplier Part Number 1=565-3200-1-ND, Tolerance_%=20%, Value1="0.025 ohm", Value2=10V, ValueDisplayed=120uF
C12: library part CMP-0009670-3, "CAP, CERM, 0.1 uF, 16 V, +/- 10%, X5R, 0201", Cap_Case=0201, Manufacturer=MuRata, Supplier Part Number 1=490-10387-1-ND, TempCo=X5R, Tolerance_%=10%, Value1=Unknown, Value2=16V, ValueDisplayed=0.1uF
C13 C59: library part CMP-0007995-2, "CAP, CERM, 10 uF, 16 V, +/- 10%, X7R, 0805", Cap_Case=0805, Manufacturer="Samsung Electro-Mechanics", TempCo=X7R, Tolerance_%=10%, Value1=Unknown, Value2=16V, ValueDisplayed=10uF
C14 C15 C16 C17 C60 C61 C62 C63 C82_USB1 C82_USB2 C85_USB1 C85_USB2 C87 C89 C100_USB1 C100_USB2: library part CMP-0086059-1, "CAP, CERM, 0.1 µF, 10 V,+/- 10%, X5R, 0201", Cap_Case=0201, Manufacturer=MuRata, TempCo=X5R, Tolerance_%=10%, Value2=10V, ValueDisplayed=0.1µF
C18 C19 C21 C22 C32 C33 C34 C35 C38 C39 C68 C69 C73 C75 C76 C77 C84: library part CMP-0009635-3, "CAP, CERM, 0.33 uF, 10 V, +/- 10%, X5R, 0201", Cap_Case=0201, Manufacturer=TDK, Supplier Part Number 1=445-13662-1-ND, TempCo=X5R, Tolerance_%=10%, Value1=Unknown, Value2=10V, ValueDisplayed=0.33uF
C20 C23 C65 C66: library part CMP-0007844-2, "CAP, CERM, 22 uF, 35 V, +/- 20%, X5R, 0805", Cap_Case=0805, Manufacturer=TDK, Supplier Part Number 1=445-14428-1-ND, TempCo=X5R, Tolerance_%=20%, Value1="0.00205 ohm", Value2=35V, ValueDisplayed=22uF
C24 C25 C26 C27 C28 C29 C30 C31 C64 C67 C70 C71 C72 C74 C78 C79: library part CMP-0009781-1, "CAP, CERM, 0.22 uF, 10 V, +/- 20%, X5R, 0201", Cap_Case=0201, Manufacturer="Taiyo Yuden", Supplier Part Number 1=587-2483-1-ND, TempCo=X5R, Tolerance_%=20%, Value1=Unknown, Value2=10V, ValueDisplayed=0.22uF
C36 C37 C105 C106 C107 C108 C110 C116: library part CMP-0064970-1, "CAP, CERM, 0.1 uF, 16 V,+/- 10%, X7R, 0201", Cap_Case=0201, Manufacturer=MuRata, Supplier Part Number 1=81-GRM033Z71C104KE4D, TempCo=X7R, Tolerance_%=10%, Value1=Unknown, Value2=16V, ValueDisplayed=0.1uF
C40_V1 C40_V2 C41_V1 C41_V2 C48_V1 C48_V2 C49_V1 C49_V2 C50_V1 C50_V2 C51_V1 C51_V2: library part CMP-0085951-1, "CAP, CERM, 10 µF, 75 V,+/- 20%, X7R, AEC-Q200 Grade 1, 1210", Cap_Case=1210, Manufacturer=TDK, TempCo=X7R, Tolerance_%=20%, Value2=75V, ValueDisplayed=10µF
C42_V1 C42_V2 C45_V1 C45_V2 C47_V1 C47_V2 C122_DS1 C122_DS2: library part CMP-0081784-1, "CAP, CERM, 1 µF, 50 V,+/- 20%, X5R, AEC-Q200 Grade 3, 0603", Cap_Case=0603, Manufacturer=MuRata, Supplier Part Number 1=490-12331-1-ND, TempCo=X5R, Tolerance_%=20%, Value2=50V, ValueDisplayed=1µF
C43_V1 C43_V2: library part CMP-0012579-3, "CAP, Polymer Hybrid, 68 uF, 50 V, +/- 20%, 30 ohm, 8x10 SMD", Manufacturer=Panasonic, Supplier Part Number 1=P15445CT-ND, Tolerance_%=20%, Value1="30 ohm", Value2=50V, ValueDisplayed=68uF
C44_V1 C44_V2 C46_V1 C46_V2 C54_V1 C54_V2 C80_V1 C80_V2: library part CMP-0086535-1, "0.1µF ±10% 50V Ceramic Capacitor X8L 0603 (1608 Metric)", Manufacturer="Murata Electronics North America", TempCo=-40+15%, Tolerance_%=0.1
C52_V1 C52_V2: library part CMP-0012571-3, "CAP, Polymer Hybrid, 220 uF, 25 V, +/- 20%, 27 ohm, 8x10 SMD", Manufacturer=Panasonic, Supplier Part Number 1=P15437CT-ND, Tolerance_%=20%, Value1="27 ohm", Value2=25V, ValueDisplayed=220uF
C53_V1 C53_V2 C123_DS1 C123_DS2: library part CMP-0006325-2, "CAP, CERM, 0.1 uF, 50 V, +/- 10%, X7R, AEC-Q200 Grade 1, 0402", Cap_Case=0402, Manufacturer=TDK, Supplier Part Number 1=445-6899-1-ND, TempCo=X7R, Tolerance_%=10%, Value1="0.039064 ohm", Value2=50V, ValueDisplayed=0.1uF
C55_V1 C55_V2: library part CMP-0006324-2, "CAP, CERM, 0.01 uF, 50 V, +/- 10%, X7R, AEC-Q200 Grade 1, 0402", Cap_Case=0402, Manufacturer=TDK, Supplier Part Number 1=445-6893-1-ND, TempCo=X7R, Tolerance_%=10%, Value1="0.333065 ohm", Value2=50V, ValueDisplayed=0.01uF
C56_V1 C56_V2: library part CMP-0081052-1, "CAP, CERM, 4.7 µF, 16 V,+/- 10%, X5R, AEC-Q200 Grade 3, 0603", Cap_Case=0603, Manufacturer=MuRata, Supplier Part Number 1=490-12319-1-ND, TempCo=X5R, Tolerance_%=10%, Value2=16V, ValueDisplayed=4.7µF
C57_V1 C57_V2: library part CMP-0006308-2, "CAP, CERM, 100 pF, 50 V, +/- 5%, C0G/NP0, AEC-Q200 Grade 1, 0402", Cap_Case=0402, Manufacturer=TDK, Supplier Part Number 1=445-5596-1-ND, TempCo=C0G/NP0, Tolerance_%=5%, Value1=Unknown, Value2=50V, ValueDisplayed=100pF
C58_V1 C58_V2: library part CMP-0006321-2, "CAP, CERM, 4700 pF, 50 V, +/- 10%, X7R, AEC-Q200 Grade 1, 0402", Cap_Case=0402, Manufacturer=TDK, Supplier Part Number 1=445-5607-1-ND, TempCo=X7R, Tolerance_%=10%, Value1="0.413508 ohm", Value2=50V, ValueDisplayed=4700pF
C83_USB1 C83_USB2: library part CMP-0006868-5, "CAP, CERM, 1 uF, 16 V, +/- 10%, X5R, 0603", Cap_Case=0603, Manufacturer=Kemet, Supplier Part Number 1=399-5090-1-ND, TempCo=X5R, Tolerance_%=10%, Value1=Unknown, Value2=16V, ValueDisplayed=1uF
C88_DS1 C88_DS2: library part CMP-0007995-2, "CAP, CERM, 10 uF, 50V V, +/- 10%, X7R, 0805", Cap_Case=0805, Manufacturer="Samsung Electro-Mechanics", TempCo=X7R, Tolerance_%=10%, Value1=Unknown, Value2=16V, ValueDisplayed=10uF
C90 C91 C92 C93: library part CMP-0011556-2, "CAP, TA, 100 uF, 6.3 V, +/- 20%, 0.015 ohm, SMD", Cap_Case=3528-21, Manufacturer=Kemet, Supplier Part Number 1=399-5306-1-ND, Tolerance_%=20%, Value1="0.015 ohm", Value2=6.3V, ValueDisplayed=100uF
C94 C95 C96 C97: library part CMP-0078699-1, "CAP, CERM, 47 µF, 10 V,+/- 20%, X5R, 0805", Cap_Case=0805, Manufacturer=MuRata, Supplier Part Number 1=490-9961-1-ND, TempCo=X5R, Tolerance_%=20%, Value2=10V, ValueDisplayed=47µF
C98 C99: library part CMP-0006552-2, "CAP, CERM, 4.7 uF, 6.3 V, +/- 20%, X5R, 0402", Cap_Case=0402, Manufacturer=MuRata, Supplier Part Number 1=490-5915-1-ND, TempCo=X5R, Tolerance_%=20%, Value1=Unknown, Value2=6.3V, ValueDisplayed=4.7uF
C101: library part CMP-0011214-2, "CAP, AL, 220 uF, 63 V, +/- 20%, 0.16 ohm, AEC-Q200 Grade 2, SMD", Cap_Case=H13, Manufacturer=Panasonic, Supplier Part Number 1=PCE3484CT-ND, Tolerance_%=20%, Value1="0.16 ohm", Value2=63V, ValueDisplayed=220uF
C102: library part CMP-0006356-2, "CAP, CERM, 0.1 uF, 50 V, +/- 10%, X7R, AEC-Q200 Grade 1, 0402", Cap_Case=0402, Manufacturer=MuRata, Supplier Part Number 1=490-10672-1-ND, TempCo=X7R, Tolerance_%=10%, Value1=Unknown, Value2=50V, ValueDisplayed=0.1uF
C103: library part CMP-0007356-5, "CAP, CERM, 2.2 uF, 35 V, +/- 10%, X5R, 0603", Cap_Case=0603, Manufacturer=MuRata, Supplier Part Number 1=490-7204-6-ND, TempCo=X5R, Tolerance_%=10%, Value1=Unknown, Value2=35V, ValueDisplayed=2.2uF
C109_US1 C109_US2: library part CMP-0007357-5, "CAP, CERM, 4.7 uF, 35 V, +/- 10%, X5R, 0603", Cap_Case=0603, Manufacturer=MuRata, Supplier Part Number 1=490-7205-1-ND, TempCo=X5R, Tolerance_%=10%, Value1=Unknown, Value2=35V, ValueDisplayed=4.7uF
C111_US1 C111_US2 C115 C118_DS1 C118_DS2 C119_DS1 C119_DS2 C120_DS1 C120_DS2 C121_DS1 C121_DS2 C124_US1 C124_US2 C125_US1 C125_US2 C126_US1 C126_US2 C130 C131: library part CMP-0006236-2, "CAP, CERM, 0.01 uF, 50 V, +/- 5%, X7R, 0402", Cap_Case=0402, Manufacturer=Kemet, Supplier Part Number 1=399-7758-1-ND, TempCo=X7R, Tolerance_%=5%, Value1=Unknown, Value2=50V, ValueDisplayed=0.01uF
C112: library part CMP-0006770-4, "CAP, CERM, 180 pF, 50 V, +/- 5%, C0G/NP0, 0603", Cap_Case=0603, Manufacturer=AVX, Supplier Part Number 1=478-1178-1-ND, TempCo=C0G/NP0, Tolerance_%=5%, Value1="0.09 ohm", Value2=50V, ValueDisplayed=180pF
C113 C114: library part CMP-0009661-3, "CAP, CERM, 10 pF, 25 V, +/- 5%, C0G/NP0, 0201", Cap_Case=0201, Manufacturer=MuRata, Supplier Part Number 1=GJM0335C1E100JB01D-ND, TempCo=C0G/NP0, Tolerance_%=5%, Value1=Unknown, Value2=25V, ValueDisplayed=10pF
C127 C128: library part CMP-0009780-1, "CAP, CERM, 4.7 uF, 6.3 V, +/- 20%, X5R, 0201", Cap_Case=0201, Manufacturer=MuRata, Supplier Part Number 1=490-13230-1-ND, TempCo=X5R, Tolerance_%=20%, Value1=Unknown, Value2=6.3V, ValueDisplayed=4.7uF
C129: library part CMP-0008646-2, "CAP, CERM, 47 uF, 25 V, +/- 20%, JB, 1206", Cap_Case=1206, Manufacturer=TDK, Supplier Part Number 1=445-11717-1-ND, TempCo=JB, Tolerance_%=20%, Value1=Unknown, Value2=25V, ValueDisplayed=47uF
D1 D2 D10 D11 D12 D15 D16 D17 D18 D20 D21: library part CMP-0002894-2, "LED, Green, SMD", Color=green, Manufacturer="Wurth Elektronik", Value1=W, Value2=2V
D9: library part CMP-0006061-5, "Diode, TVS, Bi, 24 V, 70 Vc, SOD323", Manufacturer="NXP Semiconductor", Value1=200W
D13_DS1 D13_DS2 D14_US1 D14_US2: library part CMP-0028829-2, "Diode, Schottky, 30 V, 2 A, 2-XFDFN", Manufacturer="ON Semiconductor", Value1=2A, Value2=0.48V
D19: library part CMP-0073609-3, "1-Channel ESD Protection Diode With Low Dynamic Resistance and Low Clamping Voltage, DPY0002A (X1SON-2)", Alternate Manufacturer="Texas Instruments", Alternate PartNumber=TPD1E1B04DPYT, Operating Temperature Range="-40 to 125 C", Rating=Catalog
FID1 FID2 FID3 FID4 FID5 FID6: library part CMP-0077181-1, "Fiducial mark.  There is nothing to buy or mount.", Manufacturer=N/A
H1 H2 H3 H4: library part CMP-0003617-1, "Machine Screw, Round, #4-40 x 1/4, Nylon, Philips panhead", Manufacturer="B&F Fastener Supply", Supplier Part Number 1=H542-ND
J4: library part CMP-0084861-2, "Banana Jack BIL 20 Red, TH", Color=Red, Current_A=32A, Manufacturer=Hirschmann, Voltage_V=60V
J6: library part CMP-0054798-2, "Header, 2.54 mm, 4x1, Gold, TH", Color=Black, Manufacturer="Wurth Elektronik", Supplier Part Number 1=732-5317-ND
J7: library part CMP-0065029-1, "Connector, Receptacle, USB Micro B, R/A, SMT", Color=Black, Manufacturer=FCI, Supplier Part Number 1=609-4616-1-ND
J8_US1 J8_US2 J9_DS1 J9_DS2: library part CMP-0093331-1, "USB-C (USB TYPE-C) USB 3.2 Gen 2 (USB 3.1 Gen 2, Superspeed + (USB 3.1)) Receptacle Connector 24 Position Board Edge, Cutout; Surface Mount; Through Hole, Right Angle", Current_A=5A, Digikey Part Number=732-13723-1-ND, Manufacturer="Wurth Electronics", Mouser Part Number=710-632723130112, Operating Temperature Range="-40°C to +85°C", Voltage_V=20V
J10: library part CMP-0054806-3, "Header, 2.54 mm, 5x2, Gold, TH", Current_A=3A, Manufacturer="Wurth Elektronik", Supplier Part Number 1=732-2672-ND, Voltage_V=250V
J11: library part CMP-0079535-2, "Header, 2.54mm, 4x2, Gold, SMT", Color=Black, Current_A=3A, Manufacturer="Wurth Elektronik", Supplier Part Number 1=732-5462-5-ND, Voltage_V=250V
J13 J14: library part CMP-0054794-2, "Header, 2.54 mm, 2x1, Gold, TH", Color=Black, Manufacturer="Wurth Elektronik", Supplier Part Number 1=732-5315-ND
J15: library part CMP-0084860-2, "Banana Jack BIL 20 Black, TH", Color=Black, Current_A=32A, Manufacturer=Hirschmann, Voltage_V=60V
L2_DS1 L2_DS2 L5_US1 L5_US2: library part CMP-0003072-1, "Ferrite Bead, 22 ohm @ 100 MHz, 6 A, 0805", Manufacturer="Wurth Elektronik", Supplier Part Number 1=732-4637-1-ND, Value1="0.008 ohm", Value2=6A, ValueDisplayed="22 ohm"
L3_V1 L3_V2: library part CMP-0060950-1, "Inductor, Shielded, Composite, 4.7 uH, 24 A, 0.01 ohm, SMD", Manufacturer=Coilcraft, Supplier Part Number 1=994-XAL1010-472MEB, Value1="0.01 ohm", Value2=24A, ValueDisplayed=4.7uH
L4_USB1 L4_USB2: library part CMP-0003095-1, "Ferrite Bead, 100 ohm @ 100 MHz, 1 A, 0805", Manufacturer="Wurth Elektronik", Supplier Part Number 1=732-4624-1-ND, Value1="0.15 ohm", Value2=1A, ValueDisplayed="100 ohm"
L6: library part CMP-0063942-1, "Inductor, Shielded Drum Core, Superflux, 3.3 uH, 8 A, 0.0096 ohm, SMD", Manufacturer="Wurth Elektronik", Supplier Part Number 1=732-1160-1-ND, Value1="0.0096 ohm", Value2=8A, ValueDisplayed=3.3uH
L7: library part CMP-0003155-2, "Ferrite Bead, 26 ohm @ 100 MHz, 6.5 A, 0603", Manufacturer="Wurth Elektronik", Supplier Part Number 1=732-6117-1-ND, Value1="0.005 ohm", Value2=6.5A, ValueDisplayed="26 ohm"
L8: library part CMP-0064074-1, "Inductor, Shielded Drum Core, Powdered Iron, 2.2 uH, 3.25 A, 0.051 ohm, SMD", Manufacturer="Wurth Elektronik", Supplier Part Number 1=732-3331-1-ND, Value1="0.051 ohm", Value2=3.25A, ValueDisplayed=2.2uH
Logo1: library part CMP-0074838-1, "Texas Instrument Corporate Signature"
Logo2: library part CMP-0074844-1
Logo4: library part CMP-0074769-1
Logo100: library part CMP-0074847-1, "FCC_disclaimer"
NT1_V1 NT1_V2 NT2_USB1 NT2_USB2 NT3_USB1 NT3_USB2 NT4 NT5: library part CMP-0078142-4, "Single point connection between nets.", Manufacturer=N/A
Q3_V1 Q3_V2 Q4_V1 Q4_V2 Q7: library part CMP-0000714-1, "MOSFET, N-CH, 40 V, 100 A, DQJ0008A (VSONP-8)", Alternate Manufacturer=None, Manufacturer="Texas Instruments", Supplier Part Number 1=296-45231-1-ND, Value1=0.004, Value2="47 nC"
Q5 Q6: library part CMP-0000596-1, "MOSFET, 2-CH, N-CH, 30 V, 20 A, DQZ0008A (LSON-CLIP-8)", Alternate Manufacturer=None, Manufacturer="Texas Instruments", Supplier Part Number 1=296-29660-1-ND, Value1=0.011, Value2="4.8 nC"
R1 R2 R5 R8 R11 R17 R18 R19 R20 R25 R26 R27 R31 R32 R92 R102 R106 R111 R112 R125 R126 R130 R131 R136 R137 R138 R162 R165 R169: library part CMP-0027262-3, "RES, 10.0 k, 1%, 0.05 W, 0201", Manufacturer=Vishay-Dale, Power_W=50mW, Supplier Part Number 1=541-10.0KAABCT-ND, TempCo="100 ppm/C", Tolerance_%=1%, Value2=0.05W, Value_Code=10k0, ValueDisplayed=10.0k
R3 R4 R6 R7 R9 R10: library part CMP-0027272-3, "RES, 2.20 k, 1%, 0.05 W, 0201", Manufacturer=Vishay-Dale, Power_W=50mW, Supplier Part Number 1=541-2.20KAABCT-ND, TempCo="100 ppm/C", Tolerance_%=1%, Value2=0.05W, Value_Code=2k20, ValueDisplayed=2.20k
R12 R21: library part CMP-0027730-1, "RES, 499 k, 1%, 0.05 W, 0201", Manufacturer="Yageo America", Power_W=50mW, Supplier Part Number 1=YAG2699CT-ND, TempCo="200 ppm/C", Tolerance_%=1%, Value2=0.05W, Value_Code=499k
R13 R22: library part CMP-0027786-1, "RES, 59.0 k, 1%, 0.05 W, 0201", Manufacturer="Yageo America", Power_W=50mW, Supplier Part Number 1=YAG2739CT-ND, TempCo="200 ppm/C", Tolerance_%=1%, Value2=0.05W, Value_Code=59k0, ValueDisplayed=59.0k
R14 R15: library part CMP-0027575-1, "RES, 2.21, 1%, 0.05 W, 0201", Manufacturer="Yageo America", PartNumber=RC0201FR-072R21L, Power_W=50mW, Supplier Part Number 1=RC0201FR-072R21L-ND, TempCo="350 ppm/C", Tolerance_%=1%, Value2=0.05W, Value_Code=2R21, ValueDisplayed=2.21
R16: library part CMP-0080844-1, "RES, 15.4 k, 1%, 0.05 W, 0201", Manufacturer=Vishay-Dale, Power_W=50mW, Supplier Part Number 1=541-15.4KAABCT-ND, TempCo="100 ppm/C", Tolerance_%=1%, Value2=0.05W, Value_Code=15k4, ValueDisplayed=15.4k
R23: library part CMP-0027845-1, "RES, 6.49 k, 1%, 0.05 W, 0201", Manufacturer="Yageo America", Power_W=50mW, Supplier Part Number 1=YAG2782CT-ND, TempCo="200 ppm/C", Tolerance_%=1%, Value2=0.05W, Value_Code=6k49, ValueDisplayed=6.49k
R24 R30 R37 R45 R46 R47 R54 R56 R57 R59 R60 R61 R108 R109 R128 R129 R132 R133 R135 R139 R140 R144_USB1 R144_USB2 R145_USB1 R145_USB2 R146 R147 R148 R149 R150 R151 R152 R153 R154 R155 R157 R159_DS1 R159_DS2 R160_DS1 R160_DS2 R161 R171: library part CMP-0027008-4, "RES, 0, 5%, 0.05 W, 0201", Manufacturer=Vishay-Dale, Power_W=50mW, Supplier Part Number 1=72M6743, TempCo=ppm/C, Tolerance_%=5%, Value2=0.05W, Value_Code=0000, ValueDisplayed=0
R28: library part CMP-0027756-1, "RES, 51.1 k, 1%, 0.05 W, 0201", Manufacturer="Yageo America", Power_W=50mW, Supplier Part Number 1=YAG2342CT-ND, TempCo="200 ppm/C", Tolerance_%=1%, Value2=0.05W, Value_Code=51k1, ValueDisplayed=51.1k
R29: library part CMP-0025697-4, "RES, 0, 5%, 0.1 W, AEC-Q200 Grade 0, 0603", Manufacturer=Vishay-Dale, Power_W=100mW, Supplier Part Number 1=541-0.0GCT-ND, TempCo="200 ppm/C", Tolerance_%=5%, Value2=0.1W, Value_Code=0000, ValueDisplayed=0
R33 R34 R35 R36 R38 R39 R40 R41 R42 R43 R44 R50 R78 R79 R80 R81 R82 R83 R84 R85 R86 R87: library part CMP-0027267-3, "RES, 1.00 k, 1%, 0.05 W, 0201", Manufacturer=Vishay-Dale, Power_W=50mW, Supplier Part Number 1=541-1.00KAABCT-ND, TempCo="100 ppm/C", Tolerance_%=1%, Value2=0.05W, Value_Code=1k00, ValueDisplayed=1.00k
R37: library part CMP-0027269-3, "RES, 20.0 k, 1%, 0.05 W, 0201"
R51 R52 R53 R55 R58 R93 R94 R95 R96 R97 R98 R99 R100 R101 R123 R124: library part CMP-0027269-3, "RES, 20.0 k, 1%, 0.05 W, 0201", Manufacturer=Vishay-Dale, Power_W=50mW, Supplier Part Number 1=541-20.0KAABCT-ND, TempCo="100 ppm/C", Tolerance_%=1%, Value2=0.05W, Value_Code=20k0, ValueDisplayed=20.0k
R54 R56 R57 R59 R60 R61: library part CMP-0027008-4, "RES, 0, 5%, 0.05 W, 0201"
R63 R166: library part CMP-0027974-1, "RES, 1.00 M, 1%, 0.05 W, 0201", Manufacturer="Yageo America", Power_W=50mW, Supplier Part Number 1=603-RC0201FR-7D1ML, TempCo="200 ppm/C", Tolerance_%=1%, Value2=0.05W, Value_Code=1M00, ValueDisplayed=1.00M
R64 R107 R167 R170: library part CMP-0028035-1, "RES, 51.0 k, 1%, 0.05 W, 0201", Manufacturer="Yageo America", PartNumber=RC0201FR-7D51KL, Power_W=50mW, Supplier Part Number 1=603-RC0201FR-7D51KL, TempCo="200 ppm/C", Tolerance_%=1%, Value2=0.05W, Value_Code=51k0, ValueDisplayed=51.0k
R65_V1 R65_V2 R67_V1 R67_V2: library part CMP-0027472-1, "RES, 1.00, 1%, 0.05 W, 0201", Manufacturer="Yageo America", Power_W=50mW, Supplier Part Number 1=YAG3368CT-ND, TempCo="350 ppm/C", Tolerance_%=1%, Value2=0.05W, Value_Code=1R00, ValueDisplayed=1.00
R68_V1 R68_V2: library part CMP-0027358-2, "RES, 147 k, 1%, 0.05 W, 0201", Manufacturer="Yageo America", Power_W=50mW, Supplier Part Number 1=YAG2409CT-ND, TempCo="200 ppm/C", Tolerance_%=1%, Value2=0.05W, Value_Code=147k
R69_V1 R69_V2: library part CMP-0086941-2, "10 mOhms ±1% 1W Chip Resistor 1206 (3216 Metric) Automotive AEC-Q200, Current Sense, Moisture Resistant Metal Element", Manufacturer=Bourns, Power_W=1W, TempCo=50ppm/°C, Tolerance_%=1%, ValueDisplayed=10m
R70_V1 R70_V2: library part CMP-0027314-2, "RES, 115 k, 1%, 0.05 W, 0201", Manufacturer="Yageo America", Power_W=50mW, Supplier Part Number 1=YAG2382CT-ND, TempCo="200 ppm/C", Tolerance_%=1%, Value2=0.05W, Value_Code=115k
R71_V1 R71_V2: library part CMP-0027295-2, "RES, 102 k, 1%, 0.05 W, 0201", Manufacturer="Yageo America", Power_W=50mW, Supplier Part Number 1=311-102KMCT-ND, TempCo="200 ppm/C", Tolerance_%=1%, Value2=0.05W, Value_Code=102k
R72_V1 R72_V2 R77_V1 R77_V2: library part CMP-0028072-1, "RES, 10.0, 1%, 0.05 W, 0201", Manufacturer="Yageo America", Power_W=50mW, Supplier Part Number 1=603-RC0201FS-7D10RL, TempCo="350 ppm/C", Tolerance_%=1%, Value2=0.05W, Value_Code=10R0, ValueDisplayed=10.0
R73_V1 R73_V2: library part CMP-0028027-1, "RES, 49.9 k, 1%, 0.05 W, 0201", Manufacturer="Yageo America", Power_W=50mW, Supplier Part Number 1=603-RC0201FR-7D49K9L, TempCo="200 ppm/C", Tolerance_%=1%, Value2=0.05W, Value_Code=49k9, ValueDisplayed=49.9k
R74_V1 R74_V2: library part CMP-0027776-1, "RES, 56.2 k, 1%, 0.05 W, 0201", Manufacturer="Yageo America", Power_W=50mW, Supplier Part Number 1=YAG2731CT-ND, TempCo="200 ppm/C", Tolerance_%=1%, Value2=0.05W, Value_Code=56k2, ValueDisplayed=56.2k
R75_V1 R75_V2: library part CMP-0028054-1, "RES, 6.19 k, 1%, 0.05 W, 0201", Manufacturer="Yageo America", Power_W=50mW, Supplier Part Number 1=603-RC0201FR-7D6K19L, TempCo="200 ppm/C", Tolerance_%=1%, Value2=0.05W, Value_Code=6k19, ValueDisplayed=6.19k
R76_V1 R76_V2: library part CMP-0027366-2, "RES, 150 k, 1%, 0.05 W, 0201", Manufacturer="Yageo America", Power_W=50mW, Supplier Part Number 1=YAG2272CT-ND, TempCo="200 ppm/C", Tolerance_%=1%, Value2=0.05W, Value_Code=150k
R90_USB1 R90_USB2: library part CMP-0027661-1, "RES, 3.65 k, 1%, 0.05 W, 0201", Manufacturer="Yageo America", Power_W=50mW, Supplier Part Number 1=YAG2650CT-ND, TempCo="200 ppm/C", Tolerance_%=1%, Value2=0.05W, Value_Code=3k65, ValueDisplayed=3.65k
R91_USB1 R91_USB2: library part CMP-0027448-1, "RES, 1.82 k, 1%, 0.05 W, 0201", Manufacturer="Yageo America", Power_W=50mW, Supplier Part Number 1=YAG2491CT-ND, TempCo="200 ppm/C", Tolerance_%=1%, Value2=0.05W, Value_Code=1k82, ValueDisplayed=1.82k
R103_USB1 R103_USB2: library part CMP-0027335-2, "RES, 12.4 k, 1%, 0.05 W, 0201", Manufacturer="Yageo America", Power_W=50mW, Supplier Part Number 1=311-12.4KMCT-ND, TempCo="200 ppm/C", Tolerance_%=1%, Value2=0.05W, Value_Code=12k4, ValueDisplayed=12.4k
R104_USB1 R104_USB2: library part CMP-0027537-1, "RES, 27.4 k, 1%, 0.05 W, 0201", Manufacturer="Yageo America", Power_W=50mW, Supplier Part Number 1=YAG2551CT-ND, TempCo="200 ppm/C", Tolerance_%=1%, Value2=0.05W, Value_Code=27k4, ValueDisplayed=27.4k
R105 R168: library part CMP-0027574-1, "RES, 2.00 M, 1%, 0.05 W, 0201", Manufacturer="Yageo America", Power_W=50mW, Supplier Part Number 1=RC0201FR-072ML-ND, TempCo="200 ppm/C", Tolerance_%=1%, Value2=0.05W, Value_Code=2M00, ValueDisplayed=2.00M
R110 R116 R118 R156 R158 R173: library part CMP-0027719-1, "RES, 470, 1%, 0.05 W, 0201", Manufacturer="Yageo America", Power_W=50mW, Supplier Part Number 1=YAG2689CT-ND, TempCo="200 ppm/C", Tolerance_%=1%, Value2=0.05W, Value_Code=470R, ValueDisplayed=470
R113: library part CMP-0028023-1, "RES, 47.5 k, 1%, 0.05 W, 0201", Manufacturer="Yageo America", Power_W=50mW, Supplier Part Number 1=603-RC0201FR-7D47K5L, TempCo="200 ppm/C", Tolerance_%=1%, Value2=0.05W, Value_Code=47k5, ValueDisplayed=47.5k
